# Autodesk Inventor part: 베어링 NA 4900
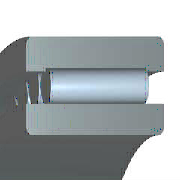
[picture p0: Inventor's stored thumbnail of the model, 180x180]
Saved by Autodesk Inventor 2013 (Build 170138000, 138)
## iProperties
Created: 2014-07
Part Number: 베어링 NA 4900
Material: Steel, Mild
Description: 니들 롤러 베어링 - 경계 치수 및 공차
Document SubType Name: Modeling
Standard: KS B 2029
Designer: KYOUNG IL JANG
Standards Organization: KS
Language: ko-KR
Size Designation: NA 4900 - 10 x 22 x 13
Categories: <MemberInstance><Categories><Category DisplayName="샤프트 부품" InternalName="7f7aeb1f-a693-4053-b835-cee3144e0d98" Mnemonic="SHFT"><Category DisplayName="베어링" Inter
Density: 1 g/cm^3
Company: 한국ATC센터
IsCustomPart: 0
Author: KYOUNG IL JANG
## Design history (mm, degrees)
sketch "스케치"
  geometry: L1 (1.857, 9)-(11.143, 9); L2 (11.143, 9)-(11.143, 7); L3 (13, 7)-(0, 7); L4 (1.857, 7)-(1.857, 9); L5 (1.857, 8)-(11.143, 8); L6 (6.5, 8)-(6.5, 7); L7 (0, 5)-(13, 5); L8 (0, 11)-(13, 11); L9 (13, 5)-(13, 7); L10 (13, 8.8)-(13, 11); L11 (1.857, 8.8)-(0, 8.8); L12 (11.143, 8.8)-(13, 8.8); L13 (-6, 0)-(36, 0) reference; L14 (0, -1.9)-(0, 14.9) reference
  constraints: 24 end point, 8 point on line, 3 midpoint, 3 parallel, 3 perpendicular, 2 symmetric about line, 1 horizontal, 1 other
  dimensions: "d6" = 10 diameter of L7 L13 (= WD); "d7" = 14 diameter of L3 L13 (= KID1); "d8" = 22 diameter of L8 L13 (= BD); "d9" = 16 diameter of L6.start L13 (= 0.5 x WD + 0.5 x BD); "d10" = 17.6 diameter of L12 L13 (= 0.9 x BD + 0.9 x WD - 0.8 x KID1); "d11" = 18 diameter of L1 L13 (= BD + WD - KID1); "d12" = 1.85714 distance between parallel lines of L14 L4 (= 0.142857 x KB); "d13" = 13 distance between parallel lines of L14 L9 (= KB); "d14" = 11.14286 distance between parallel lines of L14 L2 (= 0.857143 x KB)
revolve "본체" stored, may be unused: angle "d17" = 90 deg
revolve "롤러" stored, may be unused: angle "d18" = 90 deg
pattern_circular "IDS_ARRAYROLLER[SIMPL:T]" dims angle "d2" = 360 deg
body "Solid1"
fillet "모깎기1" dims "d0" = 0.3 (= KRS)
other parameters: "WD" = 10 [user parameter; used in 6 equation terms], "BD" = 22 [user parameter; used in 6 equation terms], "KB" = 13 [user parameter; used in 3 equation terms], "KID1" = 14 [user parameter; used in 4 equation terms], "KRS" = 0.3 [user parameter; used in 1 equation term], "d3" = 0, "d4" = 0, "d5" = 0, "d15" = 0, "d16" = 0, "BC0" = 9150000 [user parameter], "WR" = 5 (= 0.5 x WD) [user parameter], "BBA" = 0 [user parameter], "BC" = 8150000 [user parameter], "BR" = 11 (= 0.5 x BD) [user parameter]
